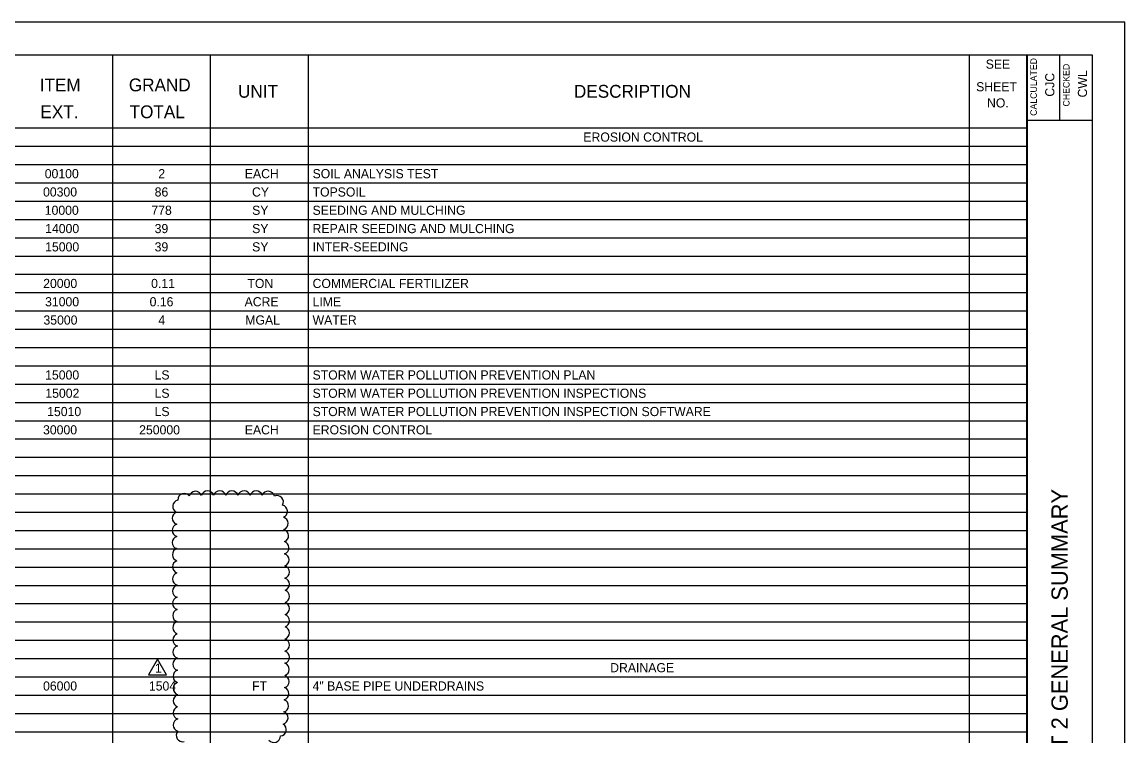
# Model space of a CAD drawing. Extents: x 0 to 34, y 0 to 22.
# Drawn here: x 17.12 to 34, y 11.08 to 22 of the extents above; entities that cross this region are included whole.
import ezdxf

# ---------------------------------------------------------------- set-up
doc = ezdxf.new("R2010")
doc.units = 0
for name, color, linetype in [('SH_Border', 7, 'Continuous'), ('SH_Cut_Line', 7, 'Continuous'), ('SH_Data', 7, 'Continuous'), ('SH_Text', 7, 'Continuous'), ('TX_P_1000', 7, 'Continuous')]:
    doc.layers.add(name, color=color, linetype=linetype)

msp = doc.modelspace()

# ---------------------------------------------------------------- linework, layer by layer
at = {"layer": 'SH_Border'}
for p, q in [((32.5, 0.5), (32.5, 21.5)), ((33, 21.5), (33, 20.5)), ((32.5, 20.5), (33.5, 20.5))]:
    msp.add_line(p, q, dxfattribs=at)
msp.add_lwpolyline([(2, 21.5), (33.5, 21.5), (33.5, 0.5), (2, 0.5)], close=True, dxfattribs=at)
at = {"layer": 'SH_Cut_Line'}
msp.add_lwpolyline([(0, 0), (34, 0), (34, 22), (0, 22)], close=True, dxfattribs=at)
at = {"layer": 'SH_Data'}
for p, q in [((15.72, 21.5), (32.504, 21.5)), ((18.504, 21.5), (18.504, 0.5)), ((20.002, 21.5), (20.002, 0.5)), ((21.501, 21.5), (21.501, 0.5)), ((31.614, 21.5), (31.614, 0.5)), ((32.504, 21.5), (32.504, 0.78)), ((2, 20.38), (32.504, 20.38)), ((2, 20.1), (32.504, 20.1)), ((2, 19.82), (32.504, 19.82)), ((2, 19.54), (32.504, 19.54)), ((2, 19.26), (32.504, 19.26)), ((2, 18.98), (32.504, 18.98)), ((2, 18.7), (32.504, 18.7)), ((2, 18.42), (32.504, 18.42)), ((2, 18.14), (32.504, 18.14)), ((2, 17.86), (32.504, 17.86)), ((2, 17.58), (32.504, 17.58)), ((2, 17.3), (32.504, 17.3)), ((2, 17.02), (32.504, 17.02)), ((2, 16.74), (32.504, 16.74)), ((2, 16.46), (32.504, 16.46)), ((2, 16.18), (32.504, 16.18)), ((2, 15.9), (32.504, 15.9)), ((2, 15.62), (32.504, 15.62)), ((2, 15.34), (32.504, 15.34)), ((2, 15.06), (32.504, 15.06)), ((2, 14.78), (32.504, 14.78)), ((2, 14.5), (32.504, 14.5)), ((2, 14.22), (32.504, 14.22)), ((2, 13.94), (32.504, 13.94)), ((2, 13.66), (32.504, 13.66)), ((2, 13.38), (32.504, 13.38)), ((2, 13.1), (32.504, 13.1)), ((2, 12.82), (32.504, 12.82)), ((2, 12.54), (32.504, 12.54)), ((2, 12.26), (32.504, 12.26)), ((2, 11.98), (32.504, 11.98)), ((2, 11.7), (32.504, 11.7)), ((2, 11.42), (32.504, 11.42)), ((2, 11.14), (32.504, 11.14))]:
    msp.add_line(p, q, dxfattribs=at)
at = {"layer": 'TX_P_1000'}
msp.add_lwpolyline([(19.194, 12.249), (19.057, 12.013), (19.33, 12.013)], close=True, dxfattribs=at)
for centre, radius, start, end in [((19.524, 14.59), 0.0975, 101.8161, 246.8161), ((19.602, 14.689), 0.0977, 36.7231, 181.7231), ((19.775, 14.722), 0.0976, 20.0252, 165.0252), ((19.96, 14.727), 0.0976, 18.0955, 163.0955), ((20.146, 14.728), 0.0976, 17.5007, 162.5007), ((20.332, 14.728), 0.0976, 17.5, 162.5), ((20.518, 14.728), 0.0976, 17.5, 162.5), ((20.704, 14.728), 0.0976, 17.4886, 162.4886), ((20.889, 14.722), 0.0976, 14.207, 159.207), ((21.023, 14.657), 0.0975, 328.8806, 113.8806), ((21.085, 14.512), 0.0976, 292.072, 77.072), ((19.516, 14.408), 0.0976, 107.7774, 252.7774), ((21.096, 14.327), 0.0976, 290.1112, 75.1112), ((19.517, 14.221), 0.0976, 107.7971, 252.7971), ((21.103, 14.141), 0.0976, 289.2389, 74.2389), ((19.518, 14.035), 0.0976, 107.805, 252.805), ((21.108, 13.955), 0.0976, 288.7142, 73.7142), ((19.519, 13.849), 0.0976, 107.8096, 252.8096), ((21.111, 13.769), 0.0976, 288.3537, 73.3537), ((19.52, 13.663), 0.0976, 107.8127, 252.8127), ((21.114, 13.583), 0.0976, 288.0863, 73.0863), ((19.521, 13.477), 0.0976, 107.815, 252.815), ((19.522, 13.29), 0.0976, 107.8168, 252.8168), ((21.115, 13.397), 0.0976, 287.8778, 72.8778), ((19.523, 13.104), 0.0976, 107.8182, 252.8182), ((21.116, 13.211), 0.0976, 287.7092, 72.7092), ((19.524, 12.918), 0.0976, 107.8194, 252.8194), ((21.117, 13.025), 0.0976, 287.5693, 72.5693), ((21.117, 12.839), 0.0976, 287.4584, 72.4584), ((19.525, 12.732), 0.0976, 107.8202, 252.8202), ((21.116, 12.653), 0.0976, 287.3535, 72.3535), ((19.526, 12.545), 0.0976, 107.8202, 252.8202), ((21.116, 12.466), 0.0976, 287.2279, 72.2279), ((19.527, 12.359), 0.0976, 107.8202, 252.8202), ((21.115, 12.28), 0.0976, 287.0737, 72.0737), ((19.528, 12.173), 0.0976, 107.8202, 252.8202), ((21.113, 12.094), 0.0976, 286.8782, 71.8782), ((19.529, 11.987), 0.0976, 107.8202, 252.8202), ((21.11, 11.908), 0.0976, 286.6187, 71.6187), ((19.53, 11.801), 0.0976, 107.8202, 252.8202), ((19.531, 11.614), 0.0976, 107.8202, 252.8202), ((21.107, 11.722), 0.0976, 286.2502, 71.2502), ((19.532, 11.428), 0.0976, 107.8202, 252.8202), ((21.102, 11.536), 0.0976, 285.6646, 70.6646), ((19.533, 11.242), 0.0976, 107.8202, 252.8202), ((21.094, 11.351), 0.0976, 284.493, 69.493), ((19.578, 11.085), 0.0976, 139.2641, 284.2641), ((21.068, 11.173), 0.0976, 273.9501, 58.9501), ((20.977, 11.072), 0.0977, 217.3339, 2.3339)]:
    msp.add_arc(centre, radius, start, end, dxfattribs=at)

# ---------------------------------------------------------------- texts
at = {"layer": 'SH_Data'}
for s, height, p in [('CALCULATED', 0.1, (32.652, 20.565)), ('CHECKED', 0.1, (33.152, 20.708)), ('CJC', 0.14, (32.92, 20.858)), ('CWL', 0.14, (33.42, 20.846)), ('4H PART 2 GENERAL SUMMARY', 0.25, (33.125, 9.672))]:
    msp.add_text(s, height=height, rotation=90, dxfattribs=at).set_placement(p)
at = {"layer": 'SH_Text'}
for s, height, p in [('SEE', 0.14, (31.869, 21.286)), ('ITEM', 0.196, (17.391, 20.94)), ('GRAND', 0.196, (18.755, 20.94)), ('UNIT', 0.196, (20.426, 20.842)), ('DESCRIPTION', 0.196, (25.567, 20.842)), ('SHEET', 0.14, (31.723, 20.94)), ('NO.', 0.14, (31.889, 20.693)), ('EXT.', 0.196, (17.401, 20.529)), ('TOTAL', 0.196, (18.767, 20.529)), ('EROSION CONTROL', 0.14, (25.711, 20.17)), ('00100', 0.14, (17.468, 19.61)), ('2', 0.14, (19.206, 19.61)), ('EACH', 0.14, (20.53, 19.61)), ('SOIL ANALYSIS TEST', 0.14, (21.567, 19.61)), ('00300', 0.14, (17.442, 19.33)), ('86', 0.14, (19.15, 19.33)), ('CY', 0.14, (20.64, 19.33)), ('TOPSOIL', 0.14, (21.567, 19.33)), ('10000', 0.14, (17.468, 19.05)), ('778', 0.14, (19.1, 19.05)), ('SY', 0.14, (20.642, 19.05)), ('SEEDING AND MULCHING', 0.14, (21.567, 19.05)), ('14000', 0.14, (17.474, 18.77)), ('39', 0.14, (19.15, 18.77)), ('SY', 0.14, (20.642, 18.77)), ('REPAIR SEEDING AND MULCHING', 0.14, (21.567, 18.77)), ('15000', 0.14, (17.474, 18.49)), ('39', 0.14, (19.15, 18.49)), ('SY', 0.14, (20.642, 18.49)), ('INTER-SEEDING', 0.14, (21.567, 18.49)), ('20000', 0.14, (17.444, 17.93)), ('0.11', 0.14, (19.096, 17.93)), ('TON', 0.14, (20.57, 17.93)), ('COMMERCIAL FERTILIZER', 0.14, (21.567, 17.93)), ('31000', 0.14, (17.473, 17.65)), ('0.16', 0.14, (19.073, 17.65)), ('ACRE', 0.14, (20.527, 17.65)), ('LIME', 0.14, (21.567, 17.65)), ('35000', 0.14, (17.448, 17.37)), ('4', 0.14, (19.206, 17.37)), ('MGAL', 0.14, (20.537, 17.37)), ('WATER', 0.14, (21.567, 17.37)), ('15000', 0.14, (17.474, 16.53)), ('LS', 0.14, (19.149, 16.53)), ('STORM WATER POLLUTION PREVENTION PLAN', 0.14, (21.567, 16.53)), ('15002', 0.14, (17.477, 16.25)), ('LS', 0.14, (19.149, 16.25)), ('STORM WATER POLLUTION PREVENTION INSPECTIONS', 0.14, (21.567, 16.25)), ('15010', 0.14, (17.505, 15.97)), ('LS', 0.14, (19.149, 15.97)), ('STORM WATER POLLUTION PREVENTION INSPECTION SOFTWARE', 0.14, (21.567, 15.97)), ('30000', 0.14, (17.442, 15.69)), ('250000', 0.14, (18.913, 15.69)), ('EACH', 0.14, (20.53, 15.69)), ('EROSION CONTROL', 0.14, (21.567, 15.69)), ('DRAINAGE', 0.14, (26.122, 12.05)), ('06000', 0.14, (17.442, 11.77)), ('1504', 0.14, (19.062, 11.77)), ('FT', 0.14, (20.642, 11.77)), ('4" BASE PIPE UNDERDRAINS', 0.14, (21.567, 11.77))]:
    msp.add_text(s, height=height, dxfattribs=at).set_placement(p)
at = {"layer": 'TX_P_1000'}
msp.add_text('1', height=0.14, rotation=360, dxfattribs=at).set_placement((19.155, 12.043))

doc.saveas('drawing.dxf')
